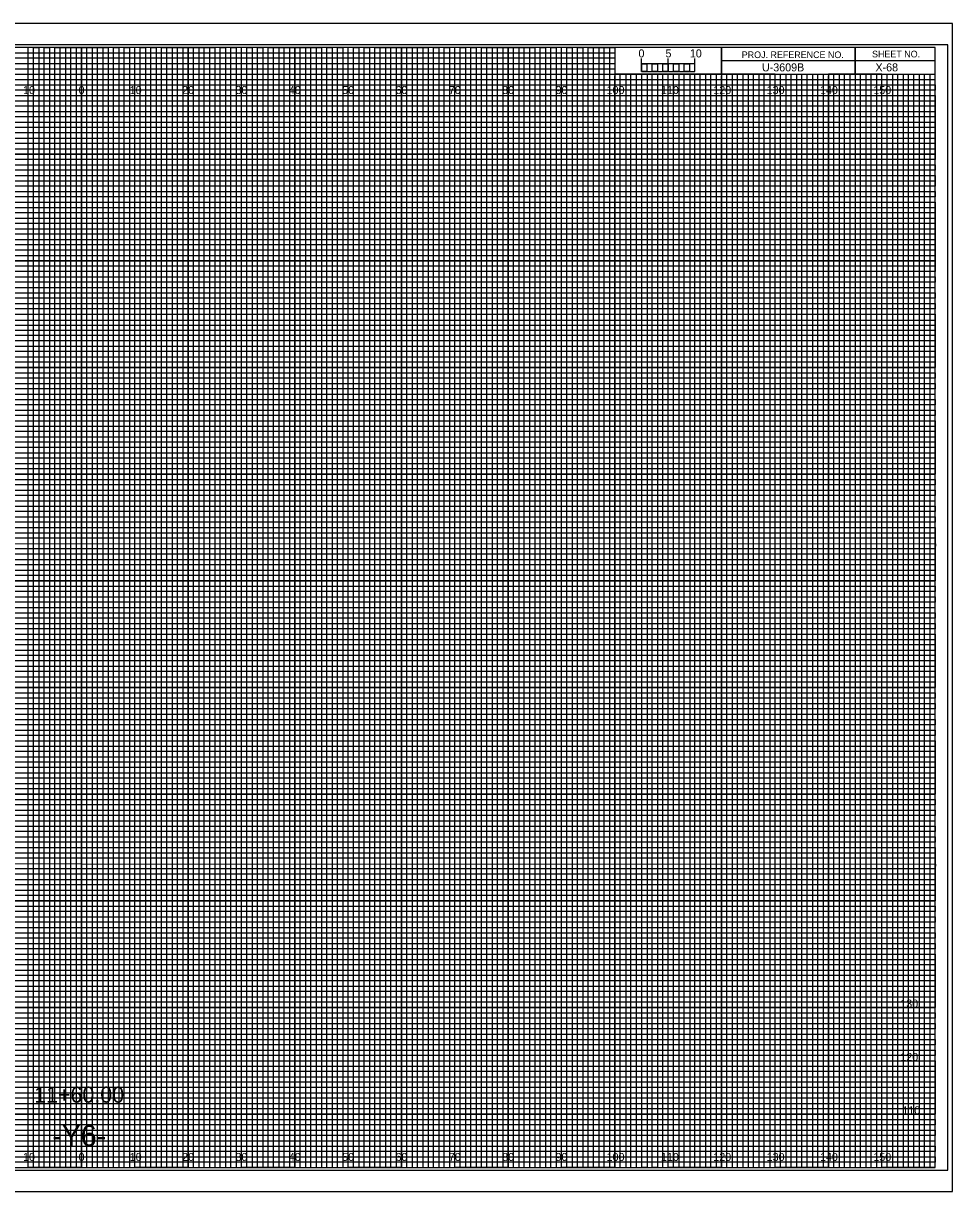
# Model space of a CAD drawing. Extents: x -13 to 323, y -5 to 434.
# Drawn here: x 149.1 to 323.3, y 215.5 to 434.5 of the extents above; entities that cross this region are included whole.
import ezdxf

# ---------------------------------------------------------------- set-up
doc = ezdxf.new("R2010")
doc.units = 0
for name, color, linetype in [('Exist CMT Pavement', 7, 'Continuous'), ('Exist Cross Section Cell', 7, 'Continuous'), ('Exist XS Center Line Elevation Label', 7, 'Continuous'), ('Exist XS Ground Line', 7, 'Continuous'), ('Prop CMT Concrete Structures', 7, 'Continuous'), ('Prop CMT Pvmt Course 1 CG', 7, 'Continuous'), ('Prop CMT Pvmt Course 1 Wedge', 7, 'Continuous'), ('Prop CMT Pvmt Course 2', 7, 'Continuous'), ('Prop CMT Pvmt Course 2 Wedge', 7, 'Continuous'), ('Prop CMT Pvmt Course 3', 7, 'Continuous'), ('Prop CMT Pvmt Course 3 Wedge', 7, 'Continuous'), ('Prop CMT Pvmt Surface', 7, 'Continuous'), ('Prop CMT Pvmt Wedge Surface 1', 7, 'Continuous'), ('Prop CMT Pvmt Wedge Surface 2', 7, 'Continuous'), ('Prop CMT Pvmt Wedge Surface 3', 7, 'Continuous'), ('Prop CMT Subgrade Earthwork', 7, 'Continuous'), ('Scratch_Level_0', 7, 'Continuous')]:
    doc.layers.add(name, color=color, linetype=linetype)

msp = doc.modelspace()

# ---------------------------------------------------------------- linework, layer by layer
at = {"layer": 'Exist XS Center Line Elevation Label'}
for points in [[(145, 220), (155, 220), (155, 430), (165, 430), (165, 220), (175, 220), (175, 430), (185, 430), (185, 220), (195, 220), (195, 430), (205, 430), (205, 220), (215, 220), (215, 430), (225, 430), (225, 220), (235, 220), (235, 430), (245, 430), (245, 220), (255, 220), (255, 430), (259.93, 430), (260, 430), (260, 425), (264.99, 425), (264.99, 220), (275, 220), (275, 425), (285, 425), (285, 220), (295, 220), (295, 425), (305, 425), (305, 220), (315, 220), (315, 425)], [(0, 425), (275, 425)], [(0, 405), (320, 405), (320, 415), (0, 415)], [(0, 385), (320, 385), (320, 395), (0, 395)], [(0, 365), (320, 365), (320, 375), (0, 375)], [(0, 345), (320, 345), (320, 355), (0, 355)], [(0, 325), (320, 325), (320, 335), (0, 335)], [(0, 305), (320, 305), (320, 315), (0, 315)], [(0, 285), (320, 285), (320, 295), (0, 295)], [(0, 265), (320, 265), (320, 275), (0, 275)], [(0, 245), (320, 245), (320, 255), (0, 255)], [(0, 225), (320, 225), (320, 235), (0, 235)]]:
    msp.add_lwpolyline(points, dxfattribs=at)
at = {"layer": 'Exist XS Ground Line'}
for p, q in [((150, 430), (140, 430)), ((150, 220), (150, 430)), ((170, 430), (160, 430)), ((160, 430), (160, 220)), ((170, 220), (170, 430)), ((190, 430), (180, 430)), ((180, 430), (180, 220)), ((190, 220), (190, 430)), ((210, 430), (200, 430)), ((200, 430), (200, 220)), ((210, 220), (210, 430)), ((230, 430), (220, 430)), ((220, 430), (220, 220)), ((230, 220), (230, 430)), ((250, 430), (240, 430)), ((240, 430), (240, 220)), ((250, 220), (250, 430)), ((260, 430), (260, 220)), ((270, 220), (270, 425)), ((290, 425), (280, 425)), ((280, 425), (280, 220)), ((290, 220), (290, 425)), ((310, 425), (300, 425)), ((300, 425), (300, 220)), ((310, 220), (310, 425)), ((160, 220), (150, 220)), ((180, 220), (170, 220)), ((200, 220), (190, 220)), ((220, 220), (210, 220)), ((240, 220), (230, 220)), ((260, 220), (250, 220)), ((280, 220), (270, 220)), ((300, 220), (290, 220)), ((320, 220), (310, 220)), ((320, 220), (320, 220))]:
    msp.add_line(p, q, dxfattribs=at)
for points in [[(0, 420), (320, 420), (320, 410), (0, 410)], [(0, 400), (320, 400), (320, 390), (0, 390)], [(0, 380), (320, 380), (320, 370), (0, 370)], [(0, 360), (320, 360), (320, 350), (0, 350)], [(0, 340), (320, 340), (320, 330), (0, 330)], [(0, 320), (320, 320), (320, 310), (0, 310)], [(0, 300), (320, 300), (320, 290), (0, 290)], [(0, 280), (320, 280), (320, 270), (0, 270)], [(0, 260), (320, 260), (320, 250), (0, 250)], [(0, 240), (320, 240), (320, 230), (0, 230)]]:
    msp.add_lwpolyline(points, dxfattribs=at)
at = {"layer": 'Prop CMT Concrete Structures'}
for p, q in [((323.3, 434.5), (-13.4, 434.5)), ((-13.4, 215.5), (323.3, 215.5))]:
    msp.add_line(p, q, dxfattribs=at)
at = {"layer": 'Prop CMT Pvmt Course 1 Wedge'}
msp.add_lwpolyline([(-13.4, 215.5), (323.3, 215.5), (323.3, 434.5), (-13.4, 434.5)], close=True, dxfattribs=at)
at = {"layer": 'Prop CMT Pvmt Course 2'}
for p, q in [((305, 430), (305, 425)), ((305, 425), (305, 430)), ((280, 427.5), (280, 425)), ((320, 427.49), (280, 427.49)), ((280, 425), (320, 425))]:
    msp.add_line(p, q, dxfattribs=at)
for points in [[(320, 430), (0, 430), (0, 220), (320, 220)], [(280, 430), (260, 430), (260, 425.03), (280, 425.03)], [(320, 430), (280, 430), (280, 425), (320, 425)]]:
    msp.add_lwpolyline(points, close=True, dxfattribs=at)
at = {"layer": 'Prop CMT Pvmt Course 2 Wedge'}
msp.add_lwpolyline([(-10.8, 219.5), (322.4, 219.5), (322.4, 430.5), (-10.8, 430.5)], close=True, dxfattribs=at)
at = {"layer": 'Prop CMT Pvmt Course 3'}
for p, q in [((267, 425), (266.01, 425)), ((266.01, 425), (266.01, 220)), ((267, 220), (267, 425)), ((269, 425), (268, 425)), ((268, 425), (268, 220)), ((269, 220), (269, 425)), ((266.01, 220), (265, 220)), ((268, 220), (267, 220))]:
    msp.add_line(p, q, dxfattribs=at)
for points in [[(150, 220), (151, 220), (151, 430), (152, 430), (152, 220)], [(152, 220), (153, 220), (153, 430), (154, 430), (154, 220)], [(155, 220), (156, 220), (156, 430), (157, 430), (157, 220)], [(157, 220), (158, 220), (158, 430), (159, 430), (159, 220)], [(160, 220), (161, 220), (161, 430), (162, 430), (162, 220)], [(162, 220), (163, 220), (163, 430), (164, 430), (164, 220)], [(165, 220), (166, 220), (166, 430), (167, 430), (167, 220)], [(167, 220), (168, 220), (168, 430), (169, 430), (169, 220)], [(170, 220), (171, 220), (171, 430), (172, 430), (172, 220)], [(172, 220), (173, 220), (173, 430), (174, 430), (174, 220)], [(175, 220), (176, 220), (176, 430), (177, 430), (177, 220)], [(177, 220), (178, 220), (178, 430), (179, 430), (179, 220)], [(180, 220), (181, 220), (181, 430), (182, 430), (182, 220)], [(182, 220), (183, 220), (183, 430), (184, 430), (184, 220)], [(185, 220), (186, 220), (186, 430), (187, 430), (187, 220)], [(187, 220), (188, 220), (188, 430), (189, 430), (189, 220)], [(190, 220), (191, 220), (191, 430), (192, 430), (192, 220)], [(192, 220), (193, 220), (193, 430), (194, 430), (194, 220)], [(195, 220), (196, 220), (196, 430), (197, 430), (197, 220)], [(197, 220), (198, 220), (198, 430), (199, 430), (199, 220)], [(200, 220), (201, 220), (201, 430), (202, 430), (202, 220)], [(202, 220), (203, 220), (203, 430), (204, 430), (204, 220)], [(205, 220), (206, 220), (206, 430), (207, 430), (207, 220)], [(207, 220), (208, 220), (208, 430), (209, 430), (209, 220)], [(210, 220), (211, 220), (211, 430), (212, 430), (212, 220)], [(212, 220), (213, 220), (213, 430), (214, 430), (214, 220)], [(215, 220), (216, 220), (216, 430), (217, 430), (217, 220)], [(217, 220), (218, 220), (218, 430), (219, 430), (219, 220)], [(220, 220), (221, 220), (221, 430), (222, 430), (222, 220)], [(222, 220), (223, 220), (223, 430), (224, 430), (224, 220)], [(225, 220), (226, 220), (226, 430), (227, 430), (227, 220)], [(227, 220), (228, 220), (228, 430), (229, 430), (229, 220)], [(230, 220), (231, 220), (231, 430), (232, 430), (232, 220)], [(232, 220), (233, 220), (233, 430), (234, 430), (234, 220)], [(235, 220), (236, 220), (236, 430), (237, 430), (237, 220)], [(237, 220), (238, 220), (238, 430), (239, 430), (239, 220)], [(240, 220), (241, 220), (241, 430), (242, 430), (242, 220)], [(242, 220), (243, 220), (243, 430), (244, 430), (244, 220)], [(245, 220), (246, 220), (246, 430), (247, 430), (247, 220)], [(247, 220), (248, 220), (248, 430), (249, 430), (249, 220)], [(250, 220), (251, 220), (251, 430), (252, 430), (252, 220)], [(252, 220), (253, 220), (253, 430), (254, 430), (254, 220)], [(255, 220), (256, 220), (256, 430), (257, 430), (257, 220)], [(257, 220), (258, 220), (258, 430), (259, 430), (259, 220)], [(260, 220), (261, 220), (261, 425), (262.02, 425), (262.02, 220)], [(262, 220), (263, 220), (263, 425), (263.99, 425), (263.99, 220)], [(270, 220), (270.98, 220), (270.98, 425), (272, 425), (272, 220)], [(272, 220), (273, 220), (273, 425), (274.05, 425), (274.05, 220)], [(275, 220), (276, 220), (276, 425), (277, 425), (277, 220)], [(277, 220), (278, 220), (278, 425), (279, 425), (279, 220)], [(280, 220), (281, 220), (281, 425), (282, 425), (282, 220)], [(282, 220), (283, 220), (283, 425), (284, 425), (284, 220)], [(285, 220), (286, 220), (286, 425), (287, 425), (287, 220)], [(287, 220), (288, 220), (288, 425), (289, 425), (289, 220)], [(290, 220), (291, 220), (291, 425), (292, 425), (292, 220)], [(292, 220), (293, 220), (293, 425), (294, 425), (294, 220)], [(295, 220), (296, 220), (296, 425), (297, 425), (297, 220)], [(297, 220), (298, 220), (298, 425), (299, 425), (299, 220)], [(300, 220), (301, 220), (301, 425), (302, 425), (302, 220)], [(302, 220), (303, 220), (303, 425), (304, 425), (304, 220)], [(305, 220), (306, 220), (306, 425), (307, 425), (307, 220)], [(307, 220), (308, 220), (308, 425), (309, 425), (309, 220)], [(310, 220), (311, 220), (311, 425), (312, 425), (312, 220)], [(312, 220), (313, 220), (313, 425), (314, 425), (314, 220)], [(315, 220), (316, 220), (316, 425), (317, 425), (317, 220)], [(317, 220), (318, 220), (318, 425), (319, 425), (319, 220)]]:
    msp.add_lwpolyline(points, dxfattribs=at)
at = {"layer": 'Prop CMT Pvmt Course 3 Wedge'}
for p, q in [((150, 220), (150, 430)), ((160, 220), (160, 430)), ((170, 220), (170, 430)), ((180, 220), (180, 430)), ((190, 220), (190, 430)), ((200, 220), (200, 430)), ((210, 220), (210, 430)), ((220, 220), (220, 430)), ((230, 220), (230, 430)), ((240, 220), (240, 430)), ((250, 220), (250, 430)), ((260, 220), (260, 424.69)), ((270, 220), (270, 424.69)), ((280, 220), (280, 424.69)), ((290, 220), (290, 424.69)), ((300, 220), (300, 424.69)), ((310, 220), (310, 424.69)), ((0, 420), (320, 420)), ((0, 410), (320, 410)), ((0, 400), (320, 400)), ((0, 390), (320, 390)), ((0, 380), (320, 380)), ((0, 370), (320, 370)), ((0, 360), (320, 360)), ((0, 350), (320, 350)), ((0, 340), (320, 340)), ((0, 330), (320, 330)), ((0, 320), (320, 320)), ((0, 310), (320, 310)), ((0, 300), (320, 300)), ((0, 290), (320, 290)), ((0, 280), (320, 280)), ((0, 270), (320, 270)), ((0, 260), (320, 260)), ((0, 250), (320, 250)), ((0, 240), (320, 240)), ((0, 230), (320, 230))]:
    msp.add_line(p, q, dxfattribs=at)
at = {"layer": 'Prop CMT Subgrade Earthwork'}
for p, q in [((265, 425.49), (265, 427.9)), ((265, 426.9), (265, 427.9)), ((270, 425.49), (270, 427.9)), ((275, 425.49), (275, 427.9)), ((275, 426.9), (275, 427.9))]:
    msp.add_line(p, q, dxfattribs=at)
for points in [[(275, 426.9), (265, 426.9), (265, 425.49), (275, 425.49)], [(265, 426.9), (266, 426.9), (266, 425.49), (265, 425.49)], [(267, 426.9), (268, 426.9), (268, 425.49), (267, 425.49)], [(269, 426.9), (270, 426.9), (270, 425.49), (269, 425.49)], [(271, 426.9), (272, 426.9), (272, 425.49), (271, 425.49)], [(273, 426.9), (274, 426.9), (274, 425.49), (273, 425.49)]]:
    msp.add_lwpolyline(points, close=True, dxfattribs=at)
at = {"layer": 'Scratch_Level_0'}
for p, q in [((0, 429), (260, 429)), ((260, 427.98), (0, 427.98)), ((260, 429), (260, 427.98)), ((0, 427), (260, 427)), ((260, 425.89), (0, 425.89)), ((260, 427), (260, 425.89)), ((0, 424), (320, 424))]:
    msp.add_line(p, q, dxfattribs=at)
for points in [[(0, 423), (270, 423), (320, 423), (320, 422), (0, 422)], [(0, 421), (320, 421), (320, 419), (0, 419)], [(0, 418), (320, 418), (320, 417), (0, 416.98)], [(0, 416), (320, 416), (320, 414), (0, 414)], [(0, 413), (320, 413), (320, 412), (0, 412)], [(0, 411), (320, 411), (320, 409), (0, 409)], [(0, 408), (320, 408), (320, 407), (0, 407)], [(0, 406), (320, 406), (320, 404), (0, 404)], [(0, 403), (320, 403), (320, 402), (0, 402)], [(0, 401), (320, 401), (320, 399), (0, 399)], [(0, 398), (320, 398), (320, 397), (0, 397)], [(0, 396), (320, 396), (320, 393.95), (320, 393), (320, 392), (0, 392)], [(0, 394), (320, 394), (320, 393), (0, 393)], [(0, 391), (320, 391), (320, 389), (0, 389.03)], [(0, 389.03), (320, 389), (320, 388), (0, 388)], [(0, 387), (320, 387), (320, 386), (0, 386)], [(0, 384), (320, 384), (320, 383), (0, 383)], [(0, 382), (320, 382), (320, 381), (0, 381)], [(-0.07, 378.89), (320, 378.89), (320, 377.88), (-0.07, 377.88)], [(0, 377), (320, 377), (320, 376), (0, 376)], [(0, 374), (320, 374), (320, 373), (0, 373)], [(0, 372), (320, 372), (320, 371), (0, 371)], [(0, 369), (320, 369), (320, 368), (0, 368)], [(0, 367), (320, 367), (320, 366), (0, 366)], [(0, 364), (320, 364), (320, 363), (0, 363)], [(0, 362), (320, 362), (320, 361), (0, 361)], [(0, 359), (320, 359), (319.99, 357.98), (0, 358)], [(0, 357), (320, 357), (320, 356), (0, 356)], [(0, 354), (320, 354), (320, 353), (0, 353)], [(0, 352), (320, 352), (320, 351), (0, 351)], [(0, 349), (320, 349), (320, 348), (0, 348)], [(0, 347), (320, 347), (320, 346), (0, 346)], [(0, 344), (320, 344), (320, 343), (0, 343)], [(0, 342), (320, 342), (320, 341), (0, 341)], [(0, 339), (320, 339), (320, 338), (0, 338)], [(0, 336.99), (320.07, 336.91), (320, 336), (0, 336)], [(0, 334), (320, 334), (320, 333), (0, 333)], [(0, 332), (320, 332), (320, 331), (0, 331)], [(0, 329), (320, 329), (320, 328), (0, 328)], [(0, 327), (320, 327), (320, 326), (0, 326)], [(0, 324), (320, 324), (320, 323), (0, 323)], [(0, 322), (320, 322), (320, 321), (0, 321)], [(0, 319), (320, 319), (320, 318), (0, 318)], [(0, 317), (320, 317), (320, 316), (0, 316)], [(0, 314), (320, 314), (320, 313), (0, 313)], [(0, 312), (320, 312), (320, 311), (0, 311)], [(0, 309), (320, 309), (320, 308), (0, 308)], [(0, 307), (320, 307), (320, 306), (0, 306)], [(0, 304), (320, 304), (320, 303), (0, 303)], [(0, 302), (320, 302), (320, 301), (0, 301)], [(0, 299), (320, 299), (319.99, 297.98), (0, 298)], [(0, 297), (320, 297), (320, 296), (0, 296)], [(0, 294), (320, 294), (320, 293), (0, 293)], [(0, 292), (320, 292), (320, 291), (0, 291)], [(0, 289), (320, 289), (320, 288), (0, 288)], [(0, 287), (320, 287), (320, 286), (0, 286)], [(0, 284), (320, 284), (320, 283), (0, 283)], [(0, 282), (320, 282), (320, 281), (0, 281)], [(0, 279), (320, 279), (320, 278), (0, 278)], [(0, 276.99), (320.07, 276.91), (320, 276), (0, 276)], [(0, 274), (320, 274), (320, 273), (0, 273)], [(0, 272), (320, 272), (320, 271), (0, 271)], [(0, 269), (320, 269), (320, 268), (0, 268)], [(0, 267), (320, 267), (320, 266), (0, 266)], [(0, 264), (320, 264), (320, 263), (0, 263)], [(0, 262), (320, 262), (320, 261), (0, 261)], [(0, 259), (320, 259), (320, 258), (0, 258)], [(0, 257), (320, 257), (320, 256), (0, 256)], [(0, 254), (320, 254), (320, 253), (0, 253)], [(0, 252), (320, 252), (320, 251), (0, 251)], [(0, 249), (320, 249), (320, 248), (0, 248)], [(0, 247), (320, 247), (320, 246), (0, 246)], [(0, 244), (320, 244), (320, 243), (0, 243)], [(0, 242), (320, 242), (320, 241), (0, 241)], [(0, 239), (320, 239), (320, 238), (0, 238)], [(0, 237), (320, 237), (320, 236), (0, 236)], [(0, 234), (320, 234), (320, 233), (0, 233)], [(0, 232), (320, 232), (320, 231), (0, 231)], [(0, 229), (320, 229), (320, 228), (0, 228)], [(0, 227), (320, 227), (320, 226), (0, 226)], [(0, 224), (320, 224), (320, 223), (0, 223)], [(0, 222), (320, 222), (320, 221), (0, 221)]]:
    msp.add_lwpolyline(points, dxfattribs=at)

# ---------------------------------------------------------------- texts
at = {"layer": 'Exist CMT Pavement'}
for s, p in [('130', (313.49, 250)), ('120', (313.5, 240)), ('110', (313.88, 230))]:
    msp.add_text(s, height=1.5, dxfattribs=at).set_placement(p)
at = {"layer": 'Exist Cross Section Cell'}
for s, p in [('10', (149.04, 421.25)), ('0', (159.45, 421.25)), ('0', (159.45, 421.25)), ('10', (169.04, 421.25)), ('20', (178.86, 421.25)), ('30', (188.86, 421.25)), ('40', (198.86, 421.25)), ('50', (208.86, 421.25)), ('60', (218.86, 421.25)), ('70', (228.86, 421.25)), ('80', (238.86, 421.25)), ('90', (248.86, 421.25)), ('100', (258.44, 421.25)), ('110', (268.62, 421.25)), ('120', (278.44, 421.25)), ('130', (288.44, 421.25)), ('140', (298.44, 421.25)), ('150', (308.44, 421.25)), ('10', (149.04, 221.25)), ('0', (159.45, 221.25)), ('0', (159.45, 221.25)), ('10', (169.04, 221.25)), ('20', (178.86, 221.25)), ('30', (188.86, 221.25)), ('40', (198.86, 221.25)), ('50', (208.86, 221.25)), ('60', (218.86, 221.25)), ('70', (228.86, 221.25)), ('80', (238.86, 221.25)), ('90', (248.86, 221.25)), ('100', (258.44, 221.25)), ('110', (268.62, 221.25)), ('120', (278.44, 221.25)), ('130', (288.44, 221.25)), ('140', (298.44, 221.25)), ('150', (308.44, 221.25))]:
    msp.add_text(s, height=1.5, dxfattribs=at).set_placement(p)
at = {"layer": 'Prop CMT Pvmt Course 1 CG'}
msp.add_text('X-68', height=1.5, dxfattribs=at).set_placement((308.83, 425.5))
at = {"layer": 'Prop CMT Pvmt Course 2'}
for s, p in [('PROJ. REFERENCE NO.', (283.77, 427.99)), ('SHEET NO.', (308.19, 428.12))]:
    msp.add_text(s, height=1.25, dxfattribs=at).set_placement(p)
at = {"layer": 'Prop CMT Pvmt Surface'}
msp.add_text('11+60.00', height=3, dxfattribs=at).set_placement((151.13, 232.18))
at = {"layer": 'Prop CMT Pvmt Wedge Surface 1'}
msp.add_text('U-3609B', height=1.5, dxfattribs=at).set_placement((287.56, 425.5))
at = {"layer": 'Prop CMT Pvmt Wedge Surface 2'}
msp.add_text('-Y6-', height=4, dxfattribs=at).set_placement((154.52, 224))
at = {"layer": 'Prop CMT Pvmt Wedge Surface 3'}
for s, p in [('5', (269.47, 428.12)), ('10', (274.04, 428.12))]:
    msp.add_text(s, height=1.5, dxfattribs=at).set_placement(p)
at = {"layer": 'Prop CMT Subgrade Earthwork'}
msp.add_text('0', height=1.5, dxfattribs=at).set_placement((264.41, 428.12))

doc.saveas('drawing.dxf')
